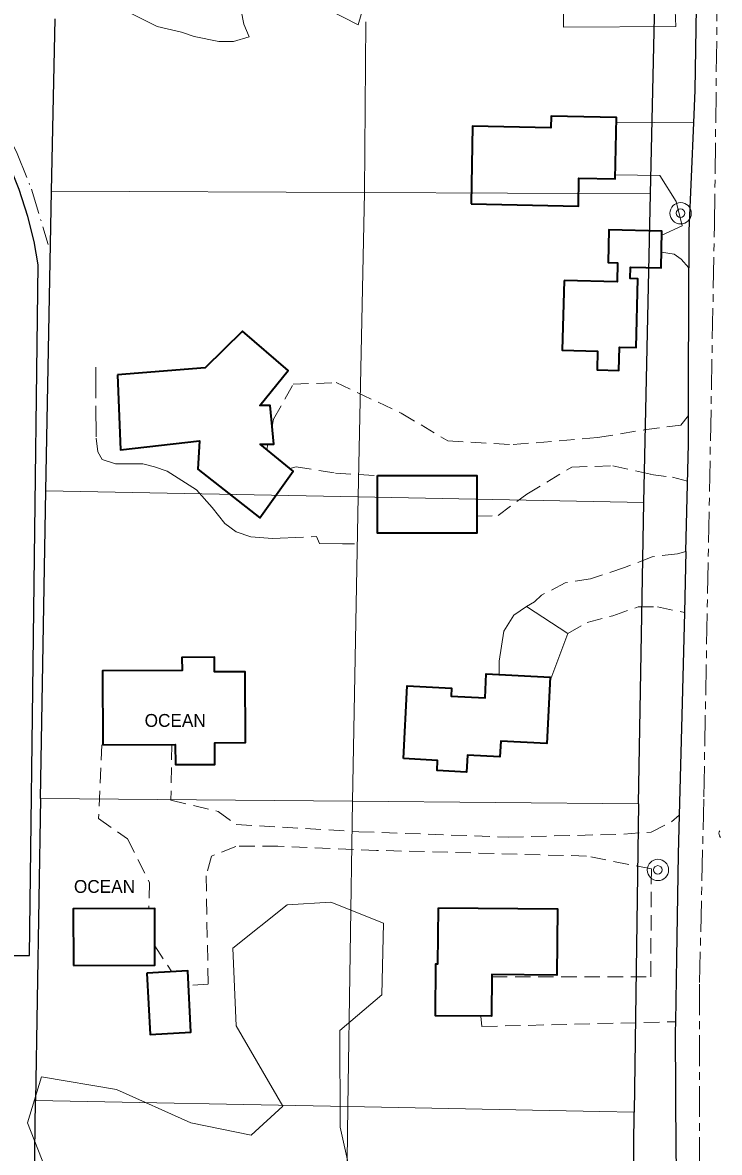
# Model space of a CAD drawing. Extents: x -861682 to -858969, y -1797841 to -1795153.
# Drawn here: x -860675 to -860350, y -1797216 to -1796688 of the extents above; entities that cross this region are included whole.
import ezdxf

# ---------------------------------------------------------------- set-up
doc = ezdxf.new("R2010")
doc.units = 0
doc.header["$LTSCALE"] = 2.4
for name, pattern in [('DOT_DASHED', [7.7, 5, -1.2, 0.3, -1.2]), ('LONG_DASH_SHORT_DASH', [9.9, 6, -1.2, 1.5, -1.2]), ('LONG_DASHED', [7.5, 6, -1.5]), ('MEDIUM_DASHED', [4.5, 3, -1.5])]:
    doc.linetypes.add(name, pattern=pattern)
for name, color, linetype, lineweight in [('10', 7, 'Continuous', 25), ('11', 7, 'Continuous', 13), ('12', 7, 'Continuous', 35), ('17', 7, 'Continuous', 13), ('18', 7, 'Continuous', 13), ('30', 7, 'Continuous', 13), ('31', 7, 'Continuous', 13), ('32', 7, 'LONG_DASH_SHORT_DASH', 13), ('42', 7, 'Continuous', 25), ('46', 7, 'Continuous', 13), ('52', 7, 'LONG_DASHED', 13), ('63', 7, 'DOT_DASHED', 13)]:
    doc.layers.add(name, color=color, linetype=linetype, lineweight=lineweight)

msp = doc.modelspace()

# ---------------------------------------------------------------- linework, layer by layer
at = {"layer": '10'}
for p, q in [((-860364.234, -1796871.828), (-860364.183, -1796802.861)), ((-860365.512, -1796935.211), (-860366.234, -1796963.764))]:
    msp.add_line(p, q, dxfattribs=at)
for points in [[(-860360.755, -1796681.521), (-860361.364, -1796719.958), (-860362.013, -1796735.14)], [(-860667.811, -1796801.476), (-860669.755, -1796790.631), (-860672.633, -1796778.858), (-860676.642, -1796766.259), (-860682.438, -1796751.966), (-860688.867, -1796739.167), (-860698.547, -1796723.507), (-860701.439, -1796719.429)], [(-860362.013, -1796735.14), (-860364.171, -1796785.621), (-860364.183, -1796802.861)], [(-860696.61, -1797098.951), (-860697.453, -1797123.953), (-860671.948, -1797123.851), (-860667.811, -1796801.476)], [(-860365.512, -1796935.211), (-860364.244, -1796885.045), (-860364.234, -1796871.828)], [(-860366.234, -1796963.764), (-860367.301, -1797005.971), (-860368.668, -1797058.398)], [(-860368.668, -1797058.398), (-860369.143, -1797076.59), (-860369.893, -1797125.005), (-860370.385, -1797154.822)], [(-860370.385, -1797154.822), (-860370.463, -1797159.487), (-860370.236, -1797215.928), (-860369.505, -1797244.965)]]:
    msp.add_lwpolyline(points, dxfattribs=at)
at = {"layer": '11'}
for p, q in [((-860397.994, -1796734.862), (-860362.013, -1796735.14)), ((-860439.984, -1796960.919), (-860420.568, -1796973.595)), ((-860428.962, -1796996.022), (-860420.568, -1796973.595))]:
    msp.add_line(p, q, dxfattribs=at)
at = {"layer": '11', "linetype": 'MEDIUM_DASHED'}
for p, q in [((-860560.602, -1796885.121), (-860561.188, -1796887.676)), ((-860613.396, -1797119.37), (-860605.437, -1797131.508))]:
    msp.add_line(p, q, dxfattribs=at)
at = {"layer": '11'}
for points in [[(-860424.171, -1796671.51), (-860422.725, -1796671.555), (-860422.649, -1796690.448), (-860370.222, -1796690.237), (-860370.488, -1796682.68), (-860360.755, -1796681.521)], [(-860398.476, -1796759.453), (-860377.736, -1796759.698), (-860370.13, -1796771.948), (-860367.251, -1796783.273), (-860376.72, -1796787.638)], [(-860376.92, -1796795.613), (-860370.976, -1796796.513), (-860367.66, -1796798.861), (-860364.183, -1796802.861)], [(-860452.609, -1796992.732), (-860452.634, -1796986.476), (-860450.564, -1796972.534), (-860445.871, -1796964.958), (-860439.984, -1796960.919)]]:
    msp.add_lwpolyline(points, dxfattribs=at)
at = {"layer": '11', "linetype": 'MEDIUM_DASHED'}
for points in [[(-860558.694, -1796876.808), (-860557.944, -1796873.541), (-860548.799, -1796857.209), (-860528.728, -1796856.42), (-860498.442, -1796870.705), (-860476.663, -1796883.606), (-860446.191, -1796885.374), (-860406.765, -1796882.145), (-860385.053, -1796878.516), (-860367.821, -1796876.321), (-860364.234, -1796871.828)], [(-860550.455, -1796896.521), (-860547.464, -1796895.698), (-860529.031, -1796898.694), (-860509.032, -1796900.023)], [(-860463.157, -1796918.82), (-860453.144, -1796918.464), (-860439.722, -1796908.492), (-860418.754, -1796895.891), (-860399.627, -1796895.342), (-860381.899, -1796899.286), (-860371.739, -1796900.662), (-860364.683, -1796902.395)], [(-860365.512, -1796935.211), (-860369.47, -1796936.313), (-860381.272, -1796937.777), (-860394.241, -1796942.788), (-860410.043, -1796948.047), (-860421.843, -1796949.984), (-860432.92, -1796955.696), (-860436.214, -1796958.779), (-860439.984, -1796960.919)], [(-860420.568, -1796973.595), (-860411.614, -1796968.363), (-860399.583, -1796965.245), (-860387.791, -1796961.183), (-860378.817, -1796961.147), (-860366.234, -1796963.764)], [(-860638.162, -1797025.471), (-860639.615, -1797059.96), (-860626.116, -1797069.352), (-860615.879, -1797089.857), (-860616.174, -1797101.9)], [(-860605.509, -1797025.34), (-860605.878, -1797051.323), (-860583.894, -1797056.666), (-860575.367, -1797062.773), (-860518.204, -1797066.087), (-860448.526, -1797068.643), (-860394.45, -1797067.245), (-860381.701, -1797066.25), (-860372.274, -1797061.489), (-860368.668, -1797058.398)], [(-860456.065, -1797133.873), (-860381.902, -1797133.791), (-860381.632, -1797083.489), (-860411.885, -1797077.47), (-860509.903, -1797074.792), (-860555.962, -1797072.85), (-860575.563, -1797072.928), (-860586.88, -1797077.461), (-860589.441, -1797086.681), (-860588.53, -1797137.217), (-860597.681, -1797137.944)], [(-860461.292, -1797152.23), (-860460.687, -1797157.014), (-860370.385, -1797154.822)]]:
    msp.add_lwpolyline(points, dxfattribs=at)
at = {"layer": '12'}
for points in [[(-860465.77, -1796773.038), (-860415.7, -1796774.018), (-860415.445, -1796761.013), (-860398.514, -1796761.345), (-860397.951, -1796732.629), (-860428.374, -1796732.033), (-860428.48, -1796737.449), (-860465.059, -1796736.733)], [(-860422.409, -1796808.76), (-860423.223, -1796841.354), (-860406.697, -1796841.767), (-860406.915, -1796850.498), (-860396.743, -1796850.752), (-860396.47, -1796839.832), (-860388.762, -1796840.025), (-860387.959, -1796807.941), (-860391.473, -1796807.853), (-860391.339, -1796802.493), (-860377.101, -1796802.849), (-860376.672, -1796785.704), (-860401.452, -1796785.084), (-860401.835, -1796800.401), (-860397.412, -1796800.512), (-860397.634, -1796809.381)], [(-860630.762, -1796852.81), (-860629.442, -1796887.757), (-860592.618, -1796883.596), (-860593.273, -1796896.824), (-860564.37, -1796919.616), (-860548.871, -1796897.827), (-860564.272, -1796885.136), (-860557.896, -1796885.11), (-860559.621, -1796867.169), (-860564.344, -1796867.188), (-860551.184, -1796850.84), (-860572.513, -1796832.504), (-860589.919, -1796849.576)], [(-860509.424, -1796899.795), (-860463.136, -1796899.846), (-860463.166, -1796926.765), (-860509.454, -1796926.713)], [(-860637.626, -1797025.469), (-860603.855, -1797025.334), (-860603.817, -1797034.78), (-860585.397, -1797034.706), (-860585.438, -1797024.552), (-860571.032, -1797024.494), (-860571.165, -1796991.432), (-860585.57, -1796991.49), (-860585.598, -1796984.641), (-860600.712, -1796984.703), (-860600.687, -1796990.842), (-860637.766, -1796990.993)], [(-860497.321, -1797031.995), (-860495.568, -1796997.981), (-860474.845, -1796999.049), (-860475.041, -1797002.856), (-860459.278, -1797003.668), (-860458.698, -1796992.418), (-860428.856, -1796993.956), (-860430.45, -1797024.882), (-860451.958, -1797023.773), (-860452.337, -1797031.127), (-860467.526, -1797030.344), (-860467.935, -1797038.272), (-860481.657, -1797037.564), (-860481.412, -1797032.815)], [(-860651.382, -1797128.491), (-860613.361, -1797128.338), (-860613.467, -1797101.889), (-860651.488, -1797102.041)], [(-860480.982, -1797101.596), (-860425.482, -1797102.082), (-860425.753, -1797133.022), (-860456.056, -1797132.757), (-860456.227, -1797152.275), (-860482.429, -1797152.045), (-860482.216, -1797127.828), (-860481.225, -1797127.837)], [(-860617.125, -1797132.134), (-860615.594, -1797160.703), (-860596.516, -1797159.681), (-860598.047, -1797131.112)]]:
    msp.add_lwpolyline(points, close=True, dxfattribs=at)
at = {"layer": '17'}
msp.add_lwpolyline([(-860349.728, -1797065.641), (-860349.966, -1797066.175), (-860350.09, -1797066.853), (-860349.888, -1797067.957), (-860349.432, -1797068.769)], dxfattribs=at)
at = {"layer": '18'}
for points in [[(-860574.562, -1796675.469), (-860571.909, -1796689.156), (-860569.287, -1796695.049), (-860576.6, -1796697.204), (-860583.449, -1796697.231), (-860595.03, -1796694.916), (-860600.942, -1796692.814), (-860612.288, -1796690.262), (-860631.22, -1796680.655)], [(-860514.343, -1796674.755), (-860518.535, -1796689.414), (-860532.734, -1796682.15)], [(-860653.251, -1797252.014), (-860672.817, -1797202.026), (-860666.29, -1797180.509), (-860631.314, -1797186.509), (-860596.536, -1797201.957), (-860568.41, -1797207.748), (-860553.586, -1797194.227), (-860575.463, -1797156.765), (-860577.025, -1797120.402), (-860551.601, -1797100.227), (-860531.296, -1797098.964), (-860506.695, -1797108.785), (-860507.506, -1797142.323), (-860527.041, -1797158.933), (-860526.86, -1797204.039), (-860519.885, -1797235.421)]]:
    msp.add_lwpolyline(points, dxfattribs=at)
at = {"layer": '30'}
for p, q in [((-860515.543, -1796767.686), (-860514.881, -1796687.977)), ((-860661.564, -1796767.058), (-860515.543, -1796767.686)), ((-860515.543, -1796767.686), (-860518.479, -1796909.727)), ((-860382.078, -1796768.361), (-860515.543, -1796767.686)), ((-860664.249, -1796906.907), (-860518.479, -1796909.727)), ((-860385.095, -1796912.446), (-860518.479, -1796909.727)), ((-860666.807, -1797050.555), (-860521.094, -1797051.843)), ((-860387.628, -1797053.158), (-860521.094, -1797051.843)), ((-860669.072, -1797191.638), (-860523.313, -1797194.394))]:
    msp.add_line(p, q, dxfattribs=at)
for points in [[(-860524.977, -1797334.488), (-860523.313, -1797194.394), (-860521.094, -1797051.843), (-860518.479, -1796909.727)], [(-860389.693, -1797197.036), (-860405.75, -1797196.707), (-860523.313, -1797194.394)]]:
    msp.add_lwpolyline(points, dxfattribs=at)
at = {"layer": '31'}
for centre, radius in [((-860367.983, -1796777.371), 5), ((-860367.983, -1796777.371), 2), ((-860378.56, -1797083.949), 5), ((-860378.56, -1797083.949), 2)]:
    msp.add_circle(centre, radius, dxfattribs=at)
at = {"layer": '32'}
msp.add_lwpolyline([(-860350.575, -1797816.671), (-860352.537, -1797784.701), (-860351.442, -1797711.343), (-860351.99, -1797541.086), (-860353.632, -1797469.37), (-860356.368, -1797360.975), (-860359.105, -1797223.017), (-860359.105, -1797136.52), (-860357.161, -1797049.888), (-860352.185, -1796782.715), (-860350.693, -1796661.317), (-860345.219, -1796479.719), (-860348.204, -1796383.696), (-860339.249, -1796324.987), (-860344.224, -1796287.673), (-860347.707, -1796239.412), (-860347.209, -1796180.704), (-860344.224, -1796130.951), (-860339.746, -1796052.839), (-860328.991, -1795893.364)], dxfattribs=at)
at = {"layer": '42'}
for p, q in [((-860382.078, -1796768.361), (-860379.978, -1796678.882)), ((-860661.564, -1796767.058), (-860659.957, -1796686.663)), ((-860664.249, -1796906.907), (-860661.564, -1796767.058)), ((-860385.095, -1796912.446), (-860382.078, -1796768.361)), ((-860666.807, -1797050.555), (-860664.249, -1796906.907)), ((-860387.628, -1797053.158), (-860385.095, -1796912.446)), ((-860666.807, -1797050.555), (-860669.072, -1797191.638)), ((-860387.628, -1797053.158), (-860389.693, -1797197.036)), ((-860671.104, -1797333.459), (-860669.072, -1797191.638)), ((-860390.81, -1797335.394), (-860389.693, -1797197.036))]:
    msp.add_line(p, q, dxfattribs=at)
at = {"layer": '52'}
msp.add_lwpolyline([(-860640.933, -1796849.311), (-860640.8, -1796882.373), (-860640.066, -1796888.746), (-860637.927, -1796892.28), (-860631.778, -1796894.381), (-860625.165, -1796894.354), (-860619.026, -1796894.33), (-860613.588, -1796895.725), (-860607.676, -1796897.827), (-860602.467, -1796901.113), (-860593.944, -1796906.51), (-860586.59, -1796914.746), (-860580.655, -1796922.28), (-860575.445, -1796926.038), (-860568.587, -1796928.372), (-860558.428, -1796929.276), (-860537.886, -1796928.249), (-860536.456, -1796931.55), (-860525.828, -1796931.743), (-860520.16, -1796931.721)], dxfattribs=at)
at = {"layer": '63'}
msp.add_lwpolyline([(-860816.097, -1796689.896), (-860747.848, -1796689.386), (-860744.303, -1796690.08), (-860734.607, -1796693.348), (-860726.327, -1796696.857), (-860712.603, -1796703.651), (-860699.098, -1796714.46), (-860687.232, -1796728.819), (-860677.703, -1796749.563), (-860671.024, -1796766.067), (-860663.127, -1796792.014)], dxfattribs=at)

# ---------------------------------------------------------------- texts
at = {"layer": '46'}
for p in [(-860618.144, -1797017.149), (-860651.144, -1797094.659)]:
    msp.add_text('OCEAN', height=6, dxfattribs=at).set_placement(p)

doc.saveas('drawing.dxf')
